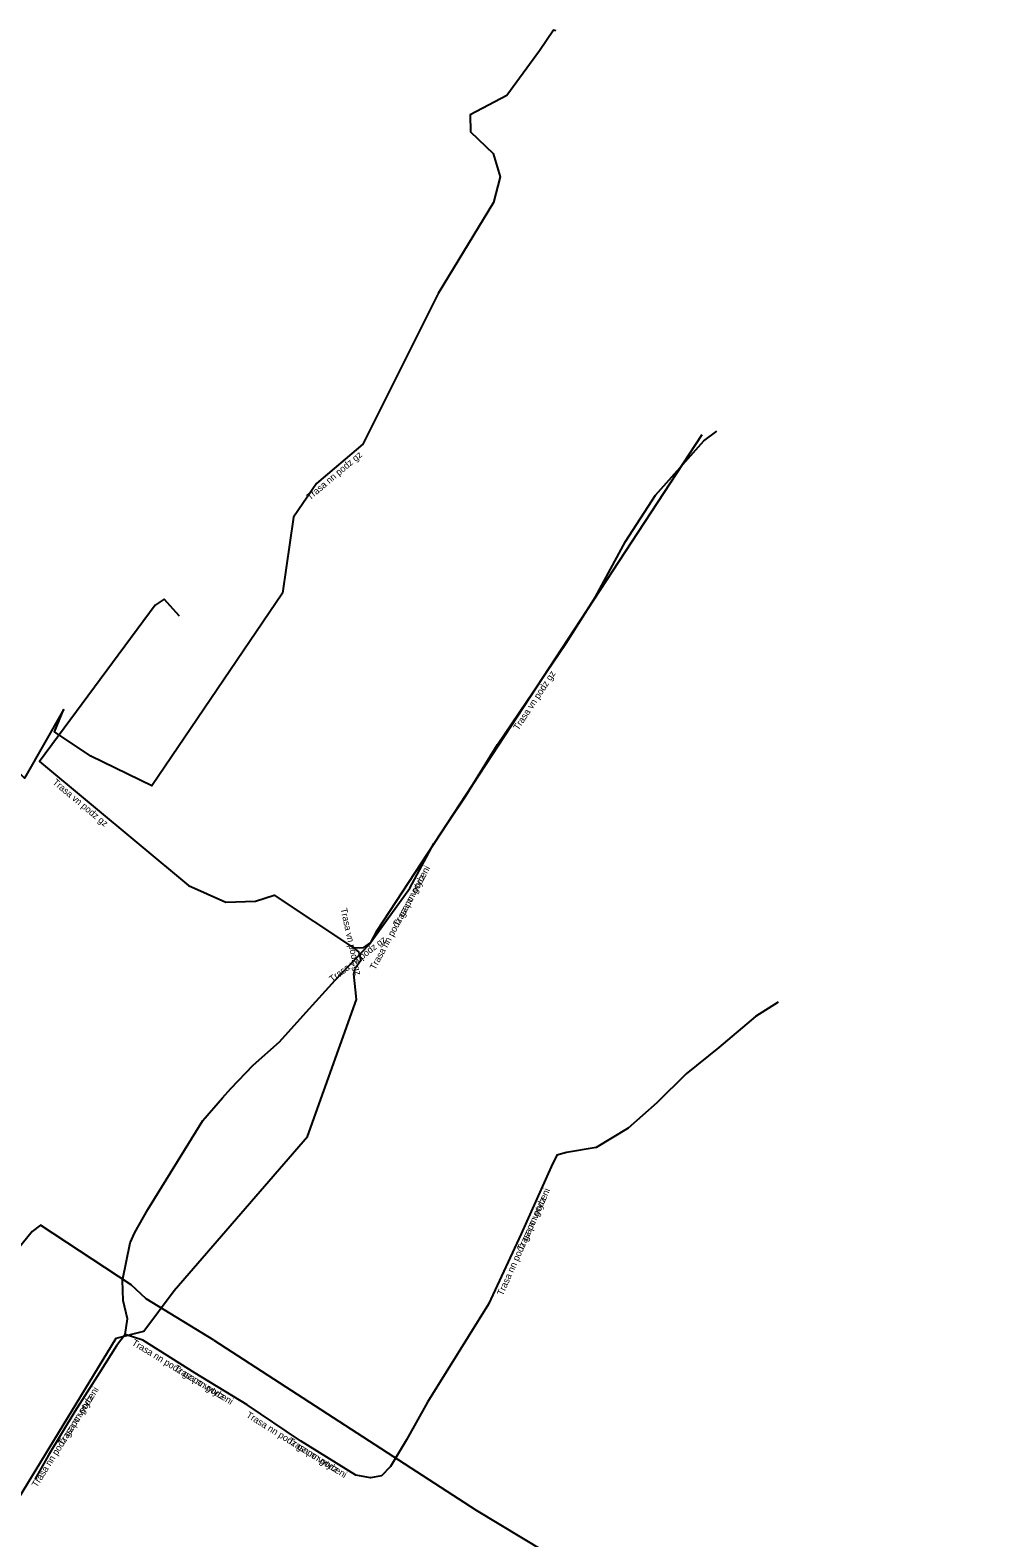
# Model space of a CAD drawing. Extents: x -747115 to -746877, y -964696 to -964505.
# Drawn here: x -747067.4 to -746996.4, y -964617.2 to -964504.6 of the extents above; entities that cross this region are included whole.
import ezdxf

# ---------------------------------------------------------------- set-up
doc = ezdxf.new("R2010")
doc.units = 0
for name, color, linetype in [('Popiskový text - Ostatní atributy Trasy', 7, 'Continuous'), ('Spojnice NN', 7, 'Continuous'), ('Spojnice VN', 7, 'Continuous')]:
    doc.layers.add(name, color=color, linetype=linetype)

msp = doc.modelspace()

# ---------------------------------------------------------------- linework, layer by layer
at = {"layer": 'Spojnice NN'}
for points in [[(-747028.05, -964504.64), (-747028.22, -964504.59), (-747029.27, -964506.14), (-747031.71, -964509.47), (-747034.45, -964510.91), (-747034.43, -964512.2), (-747032.73, -964513.8), (-747032.22, -964515.55), (-747032.72, -964517.48), (-747036.84, -964524.26), (-747042.48, -964535.53), (-747045.94, -964538.46), (-747047.67, -964540.97), (-747048.5, -964546.65), (-747058.25, -964561.06), (-747062.81, -964558.83), (-747065.54, -964557.02), (-747064.83, -964555.33)], [(-747060.25, -964602.04), (-747060.08, -964600.87), (-747060.39, -964599.5), (-747060.46, -964597.99), (-747059.88, -964595.18), (-747059.52, -964594.42), (-747058.56, -964592.69), (-747054.45, -964586.05), (-747052.98, -964584.35), (-747052.36, -964583.65), (-747050.68, -964581.91), (-747048.71, -964580.17), (-747046.72, -964577.96), (-747044.55, -964575.56), (-747042.02, -964572.91), (-747038.98, -964568.69), (-747037.18, -964565.35), (-747034.79, -964561.8), (-747032.42, -964557.96), (-747029.74, -964554.03), (-747027.28, -964550.38), (-747025.08, -964546.93), (-747022.84, -964542.8), (-747020.61, -964539.33), (-747018.36, -964536.81), (-747017, -964535.28), (-747016.03, -964534.56)], [(-747060.25, -964602.04), (-747060.08, -964600.87), (-747060.39, -964599.5), (-747060.46, -964597.99), (-747059.88, -964595.18), (-747059.52, -964594.42), (-747058.56, -964592.69), (-747054.45, -964586.05), (-747052.98, -964584.35), (-747052.36, -964583.65), (-747050.68, -964581.91), (-747048.71, -964580.17), (-747046.72, -964577.96), (-747044.55, -964575.56), (-747042.02, -964572.91), (-747038.98, -964568.69), (-747037.18, -964565.35), (-747034.79, -964561.8), (-747032.42, -964557.96), (-747029.74, -964554.03), (-747027.28, -964550.38), (-747025.08, -964546.93), (-747022.84, -964542.8), (-747020.61, -964539.33), (-747018.36, -964536.81), (-747017, -964535.28), (-747016.03, -964534.56)], [(-747064.83, -964555.33), (-747067.78, -964560.47), (-747086.32, -964542.58), (-747093.87, -964550.06), (-747096.55, -964547.36)], [(-747011.43, -964577.21), (-747013.13, -964578.29), (-747015.88, -964580.6), (-747018.31, -964582.57), (-747020.51, -964584.74), (-747022.66, -964586.63), (-747025.05, -964588.06), (-747027.26, -964588.43), (-747027.98, -964588.65), (-747028.41, -964589.51), (-747030.65, -964594.52), (-747033.08, -964599.76), (-747037.64, -964607.08), (-747039.23, -964609.91), (-747040.41, -964611.9), (-747041.09, -964612.59), (-747041.9, -964612.75), (-747043.01, -964612.54)], [(-747011.43, -964577.21), (-747013.13, -964578.29), (-747015.88, -964580.6), (-747018.31, -964582.57), (-747020.51, -964584.74), (-747022.66, -964586.63), (-747025.05, -964588.06), (-747027.26, -964588.43), (-747027.98, -964588.65), (-747028.41, -964589.51), (-747030.65, -964594.52), (-747033.08, -964599.76), (-747037.64, -964607.08), (-747039.23, -964609.91), (-747040.41, -964611.9), (-747041.09, -964612.59), (-747041.9, -964612.75), (-747043.01, -964612.54)], [(-747060.25, -964602.04), (-747060.9, -964602.88), (-747062.18, -964604.89), (-747064.02, -964607.8), (-747065.99, -964611.06), (-747067, -964612.87)], [(-747060.25, -964602.04), (-747060.9, -964602.88), (-747062.18, -964604.89), (-747064.02, -964607.8), (-747065.99, -964611.06), (-747067, -964612.87)], [(-747047.21, -964609.93), (-747051.14, -964607.29), (-747055.02, -964604.93), (-747058.92, -964602.45), (-747060.25, -964602.04)], [(-747047.21, -964609.93), (-747051.14, -964607.29), (-747055.02, -964604.93), (-747058.92, -964602.45), (-747060.25, -964602.04)], [(-747043.01, -964612.54), (-747047.14, -964609.97), (-747047.21, -964609.93)], [(-747043.01, -964612.54), (-747047.14, -964609.97), (-747047.21, -964609.93)]]:
    msp.add_lwpolyline(points, dxfattribs=at)
at = {"layer": 'Spojnice VN'}
for points in [[(-747041.42, -964571.86), (-747017.11, -964534.79)], [(-747056.18, -964548.37), (-747057.33, -964547.11), (-747058, -964547.56), (-747066.66, -964559.23), (-747055.52, -964568.5), (-747052.72, -964569.75), (-747050.51, -964569.67), (-747049.12, -964569.21), (-747043.19, -964573.16)], [(-747043.19, -964573.16), (-747042.4, -964573.13), (-747041.89, -964572.74), (-747041.42, -964571.86)], [(-747043.19, -964573.16), (-747042.77, -964573.47), (-747042.63, -964574.1), (-747043.06, -964574.7)], [(-747096.41, -964674.23), (-747099.09, -964672.73), (-747100.57, -964671.8), (-747102.04, -964670.46), (-747101.22, -964668.03), (-747100.72, -964666.88), (-747100.45, -964665.22), (-747096.65, -964657.65), (-747091.69, -964649.33), (-747088.76, -964647.93), (-747060.91, -964602.31), (-747058.85, -964601.78), (-747056.59, -964598.75), (-747046.61, -964587.25), (-747042.95, -964577), (-747043.15, -964575.1), (-747043.06, -964574.7)], [(-747053.61, -964602.45), (-747058.68, -964599.36), (-747059.8, -964598.32), (-747066.59, -964593.87), (-747067.21, -964594.33), (-747070.23, -964598.04), (-747070.27, -964599.68), (-747099.1, -964647.2), (-747100.11, -964648.07), (-747103.93, -964654.33), (-747103.64, -964655.16), (-747103.72, -964656.7), (-747104.34, -964658.34), (-747101.63, -964665.59), (-747101.16, -964666.87), (-747101.59, -964667.89), (-747102.5, -964670.58), (-747100.81, -964672.12), (-747099.3, -964673.07), (-747096.57, -964674.6)], [(-747053.61, -964602.45), (-747034.02, -964615.16), (-746967.11, -964655.47), (-746952.2, -964666.01), (-746951.01, -964667.36), (-746944.25, -964689.46), (-746943.66, -964691.51)]]:
    msp.add_lwpolyline(points, dxfattribs=at)

# ---------------------------------------------------------------- texts
at = {"layer": 'Popiskový text - Ostatní atributy Trasy'}
for s, rotation, p in [('Trasa nn podz gz', 40.2586, (-747046.43, -964539.73)), ('Trasa vn podz gz', 56.7419, (-747030.86, -964556.94)), ('Trasa vn podz gz', 320.2349, (-747065.72, -964560.86)), ('Trasa nn podz gz po vytyceni', 61.6788, (-747041.56, -964574.84)), ('Trasa nn podz', 61.6788, (-747039.81, -964571.6)), ('Trasa vn podz gz', 282.5288, (-747044.16, -964570.23)), ('Trasa vn podz gz', 37.4054, (-747044.76, -964575.75)), ('Trasa nn podz gz po vytyceni', 65.9103, (-747032.02, -964599.18)), ('Trasa nn podz', 65.9103, (-747030.52, -964595.82)), ('Trasa nn podz gz po vytyceni', 328.69, (-747059.8, -964602.78)), ('Trasa nn podz', 328.69, (-747056.65, -964604.7)), ('Trasa nn podz gz po vytyceni', 57.6947, (-747066.85, -964613.5)), ('Trasa nn podz', 57.6947, (-747064.88, -964610.38)), ('Trasa nn podz gz po vytyceni', 328.107, (-747051.25, -964608.18)), ('Trasa nn podz', 328.107, (-747048.13, -964610.12))]:
    msp.add_text(s, height=0.5, rotation=rotation, dxfattribs=at).set_placement(p)

doc.saveas('drawing.dxf')
